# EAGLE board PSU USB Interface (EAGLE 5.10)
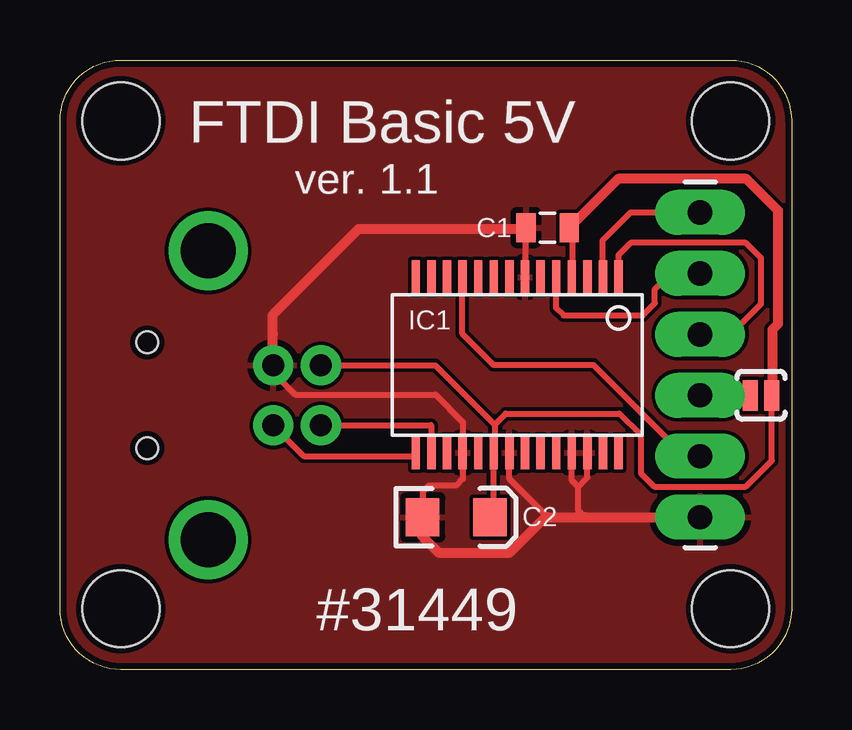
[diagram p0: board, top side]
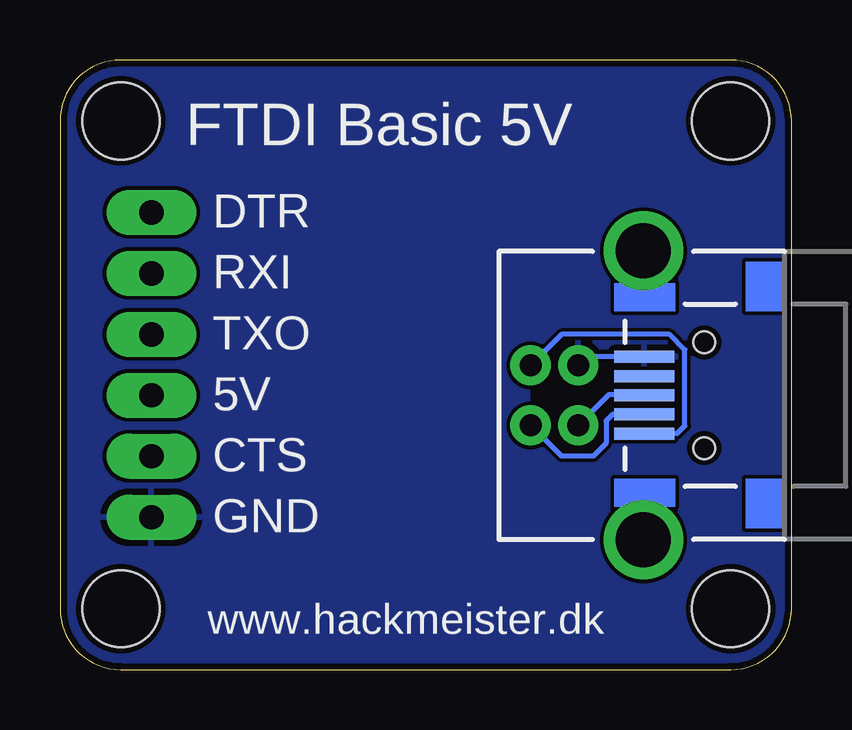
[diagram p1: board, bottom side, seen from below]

Size 30.48 x 25.4 mm. Coordinates in mm from the lower left corner, seen from the top.
Outline: 0,2.54 0,22.86 arc-90 2.54,25.4 27.94,25.4 arc-90 30.48,22.86 30.48,2.54 arc-90 27.94,0 2.54,0 arc-90 0,2.54
Copper layers (1*16): Top 0.035mm / dielectric 1.5mm / Bottom 0.035mm
Design rules "Fusion_eagle_rule_v1.1": minimum track width 6mil, minimum drill 12mil, track to track 6mil, track to pad 6mil, pad to pad 6mil, via to via 6mil, smd to smd 0mil, copper to edge 10mil, drill to drill 10mil, minimum pad ring 10mil, minimum via ring 6mil, stop-mask expansion 2mil, vias tented up to drill 100mil, thermal gap 10mil
Holes 3.2 mm at 2.54,22.86 2.54,2.54 27.94,2.54 27.94,22.86
bRestrict: area 7,9.6 to 10.9,13.3

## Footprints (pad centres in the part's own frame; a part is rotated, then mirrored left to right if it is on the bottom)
0805 = smd 0.8 x 1.2: 1 -0.9,0; 2 0.9,0
EIA3216 = smd 1.4 x 1.6: A 1.4,0; C -1.4,0
SSOP28DB = smd 0.348 x 1.397: 1 -4.225,-3.656; 2 -3.575,-3.656; 3 -2.925,-3.656; 4 -2.275,-3.656; 5 -1.625,-3.656; 6 -0.975,-3.656; 7 -0.325,-3.656; 8 0.325,-3.656; 9 0.975,-3.656; 10 1.625,-3.656; 11 2.275,-3.656; 12 2.925,-3.656; 13 3.575,-3.656; 14 4.225,-3.656; 15 4.225,3.656; 16 3.575,3.656; 17 2.925,3.656; 18 2.275,3.656; 19 1.625,3.656; 20 0.975,3.656; 21 0.325,3.656; 22 -0.325,3.656; 23 -0.975,3.656; 24 -1.625,3.656; 25 -2.275,3.656; 26 -2.925,3.656; 27 -3.575,3.656; 28 -4.225,3.656
1X06_LONGPADS = drill 1.016 pad 1.88 long: 1 0,0; 2 2.54,0; 3 5.08,0; 4 7.62,0; 5 10.16,0; 6 12.7,0
SJ_2S-NO = smd 0.635 x 1.27: 1 -0.45,0; 2 0.45,0
USB-MINIB-MOD = smd 2.5 x 0.5: D+ 2.5,0; D- 2.5,0.8; GND 2.5,-1.6; ID 2.5,-0.8; VBUS 2.5,1.6 | hole 0.9: 0,2.2; 0,-2.2
USB-B-PTH = drill 0.914 pad 1.676 round: D+ 0,1.25; D- 1.981,1.25; GND 0,-1.25; VBUS 1.981,-1.25 | drill 2.286 round: P$1 -2.718,-6.02; P$2 -2.718,6.02

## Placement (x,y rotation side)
C1  [0805]  20.32,18.41 180 top
C2  [EIA3216]  16.51,6.35 0 top
IC1  FT232RLSSOP  [SSOP28DB]  19.05,12.7 180 top
JP1  [1X06_LONGPADS]  26.67,6.35 90 top
JP2  [SJ_2S-NO]  29.21,11.43 180 top
U$3  USB  [USB-MINIB-MOD]  3.63,11.43 180 bottom
X1  USBPTH  [USB-B-PTH]  8.89,11.43 180 bottom

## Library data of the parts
C1 C2 IC1 JP1 JP2 X1 = SparkFun
U$3 = hackmeisterdk

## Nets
5V: C1.1 C2.A IC1.4 IC1.20 JP2.1 U$3.VBUS X1.VBUS
CTS: IC1.11 JP1.2
DTR: IC1.2 JP1.6
GND: C1.2 C2.C IC1.7 IC1.18 IC1.21 IC1.25 IC1.26 JP1.1 U$3.GND X1.GND
N$1: IC1.16 U$3.D- X1.D-
N$2: IC1.15 U$3.D+ X1.D+
N$3: JP1.3 JP2.2
RXI: IC1.5 JP1.5
TXO: IC1.1 JP1.4

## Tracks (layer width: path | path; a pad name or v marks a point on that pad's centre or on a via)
5V
  Top 0.254: X1.VBUS 15.64,12.68 18.11,10.21 | 18.11,10.21 18.11,9.08 IC1.20 18.06,9.03 18.06,6.96 | 21.34,18.06 21.34,16.37 IC1.4 | 18.11,10.21 18.57,10.67 23.29,10.67 24.21,9.78 24.21,8.18 24.77,7.62 28.57,7.62 29.66,8.71 JP2.1
  Top 0.406: C2.A 17.91,6.81 18.06,6.96 | 21.34,18.06 21.22,18.18 C1.1 23.25,20.45 28.6,20.45 29.92,19.13 29.92,14.4 29.69,14.17 29.69,11.46 JP2.1
  Bottom 0.203: X1.VBUS 9.58,13.97 5.08,13.97 4.45,13.34 4.45,10.16 4.78,9.83 U$3.VBUS
CTS
  Top 0.254: JP1.2 26.04,8.89 22.23,12.7 18.06,12.7 16.76,13.99 16.76,16.34 IC1.11
DTR
  Top 0.254: JP1.6 23.77,19.05 22.61,17.88 22.61,16.38 IC1.2
GND
  Top 0.254: X1.GND 8.89,12.37 9.8,11.46 15.65,11.46 16.79,10.31 16.79,9.06 IC1.18 16.79,7.95 16.51,7.67 15.37,7.67 15.11,7.41 C2.C | 19.38,17.98 IC1.7 | IC1.21 18.73,7.95 20.32,6.35 | IC1.25 21.32,7.88 21.59,7.62 | 21.59,7.62 21.59,6.63 21.87,6.35 | IC1.26 21.98,8.01 21.59,7.62
  Top 0.406: C1.2 19.42,18.02 19.38,17.98 19.38,18.36 12.45,18.36 8.87,14.78 8.87,13.97 X1.GND | JP1.1 21.87,6.35 20.32,6.35 20.22,6.35 18.75,4.88 15.77,4.88 15.09,5.56 15.09,6.33 C2.C
  Bottom 0.203: X1.GND 8.52,13.05 8.49,13.03 U$3.GND
  pour Top: 0,25.4 30.48,25.4 30.48,0 0,0
  pour Bottom: 0,25.4 30.48,25.4 30.48,0 0,0
N$1
  Top 0.254: X1.D- 13.87,10.18 15.47,10.19 15.47,9.05 IC1.16
  Bottom 0.203: X1.D- 9.58,8.89 8.26,8.89 7.72,9.42 7.72,10.36 7.46,10.63 U$3.D-
N$2
  Top 0.254: X1.D+ 8.89,10.16 10.16,8.89 14.67,8.89 IC1.15
  Bottom 0.203: X1.D+ 7.62,11.46 6.16,11.46 U$3.D+
N$3
  Top 0.406: JP1.3 JP2.2
RXI
  Top 0.254: JP1.5 25.45,16.51 24.79,15.85 24.79,15.27 24.28,14.76 20.98,14.76 20.68,15.06 IC1.5
TXO
  Top 0.254: JP1.4 27.94,13.97 29.21,15.24 29.21,17.14 28.57,17.78 23.77,17.78 23.27,17.27 IC1.1

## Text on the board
tNames: FTDI Basic 5V | ver. 1.1 | #31449
bNames: FTDI Basic 5V | DTR | RXI | TXO | 5V | CTS | GND | www.hackmeister.dk
tValues: 0.1uF | 10uF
